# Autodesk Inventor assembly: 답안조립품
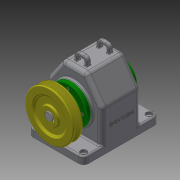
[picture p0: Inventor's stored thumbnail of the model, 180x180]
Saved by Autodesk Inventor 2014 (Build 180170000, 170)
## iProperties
Created: 2016-12
Part Number: 답안조립품
Document SubType Name: Assembly
Designer: USER
Author: USER
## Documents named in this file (14)
- C:\Users\USER\Desktop\461208V1014\답안조립품.iam
- C:\Users\USER\Desktop\461208V1014\본체.ipt
- C:\Users\USER\Desktop\461208V1014\뒤커버.ipt
- C:\Users\USER\Desktop\461208V1014\베어링 6203.ipt
- C:\Users\USER\Desktop\461208V1014\축.ipt
- C:\Users\USER\Desktop\461208V1014\키 - 6 x 6 x 22.ipt
- C:\Users\USER\Desktop\461208V1014\스퍼기어.ipt
- C:\Users\USER\Desktop\461208V1014\앞커버.ipt
- C:\Users\USER\Desktop\461208V1014\오일씰 28 40 8.ipt
- C:\Users\USER\Desktop\461208V1014\키 - 5 x 5 x 18.ipt
- C:\Users\USER\Desktop\461208V1014\V-벨트풀리.ipt
- C:\Users\USER\Desktop\461208V1014\멈춤나사 - M4x10.ipt
- C:\Users\USER\Desktop\461208V1014\볼트 M3 x 8.ipt
- C:\Users\USER\Desktop\461208V1014\볼트 M3 x 10.ipt
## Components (9 placed, 3 different names)
1. V-벨트풀리:1
2. ISO 4762 M3 x 8:1
3. ISO 4762 M3 x 8:2
4. ISO 4762 M3 x 8:3
5. ISO 4762 M3 x 8:4
6. ISO 4762 M3 x 10:1
7. ISO 4762 M3 x 10:2
8. ISO 4762 M3 x 10:3
9. ISO 4762 M3 x 10:4
